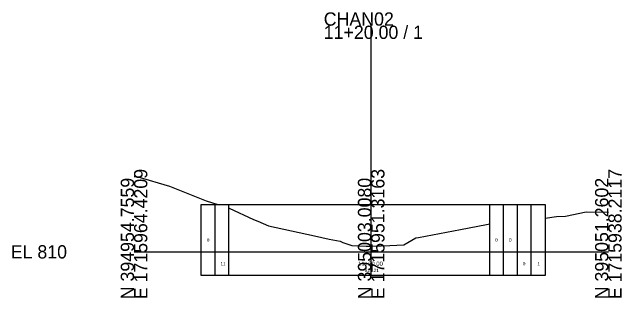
# Model space of a CAD drawing. Extents: x -26 to 103, y -10 to 16052.
# Drawn here: x -25.7 to 102.8, y 12490.3 to 12550.5 of the extents above; entities that cross this region are included whole.
import ezdxf

# ---------------------------------------------------------------- set-up
doc = ezdxf.new("R2010")
doc.units = 0
for name, color, linetype in [('GK_Cells', 7, 'Continuous'), ('SH_Text', 7, 'Continuous'), ('XS_P_Annotation', 7, 'Continuous'), ('XS_P_Boundary', 7, 'Continuous'), ('XS_X_Ground_Line', 7, 'Continuous')]:
    doc.layers.add(name, color=color, linetype=linetype)

msp = doc.modelspace()

# ---------------------------------------------------------------- linework, layer by layer
at = {"layer": 'GK_Cells'}
for p, q in [((50, 12500), (50, 12547.69)), ((0, 12500), (50, 12500)), ((50, 12500), (100, 12500))]:
    msp.add_line(p, q, dxfattribs=at)
at = {"layer": 'XS_P_Boundary'}
for p, q in [((17.08, 12495.01), (17.08, 12509.99)), ((20, 12495.01), (20, 12509.99)), ((50, 12495.01), (50, 12509.99)), ((75, 12495.01), (75, 12509.99)), ((77.92, 12495.01), (77.92, 12509.99)), ((80.83, 12495.01), (80.83, 12509.99)), ((83.75, 12495.01), (83.75, 12509.99)), ((15.63, 12502.5), (15.63, 12502.5)), ((76.46, 12502.5), (76.46, 12502.5)), ((79.38, 12502.5), (79.38, 12502.5)), ((18.54, 12497.51), (18.54, 12497.51)), ((82.29, 12497.51), (82.29, 12497.51)), ((85.21, 12497.51), (85.21, 12497.51))]:
    msp.add_line(p, q, dxfattribs=at)
msp.add_lwpolyline([(14.17, 12495.01), (14.17, 12509.99), (86.67, 12509.99), (86.67, 12495.01)], close=True, dxfattribs=at)
at = {"layer": 'XS_X_Ground_Line'}
for points in [[(0, 12515.9), (0.83, 12515.79), (7.5, 12513.87), (15.2, 12510.76), (17.64, 12509.99)], [(20, 12509.24), (20.07, 12509.22), (25.22, 12506.85), (26.13, 12506.46), (28.35, 12505.5), (38.06, 12503.35), (41.13, 12502.67), (43.44, 12502.22), (44.04, 12501.96), (45.95, 12501.32), (48.95, 12501.22), (50.27, 12501.21), (53.93, 12501.35), (56.85, 12501.48), (59.44, 12502.95), (59.96, 12503.02), (68.83, 12504.72), (74.3, 12505.75), (75, 12505.88)], [(86.67, 12507.12), (89.1, 12507.47), (90.97, 12507.55), (95.35, 12508.4), (100, 12508.35)]]:
    msp.add_lwpolyline(points, dxfattribs=at)

# ---------------------------------------------------------------- texts
at = {"layer": 'GK_Cells'}
for s, p in [('CHAN02', (40, 12547.69)), ('11+20.00 / 1', (40, 12544.89)), ('EL 810', (-26, 12498.6))]:
    msp.add_text(s, height=2.8, dxfattribs=at).set_placement(p)
for s, p in [('E 1715964.4209', (2.8, 12490)), ('E 1715951.3163', (52.8, 12490)), ('E 1715938.2117', (102.8, 12490)), ('N 394954.7559', (0, 12490)), ('N 395003.0080', (50, 12490)), ('N 395051.2602', (100, 12490))]:
    msp.add_text(s, height=2.8, rotation=90, dxfattribs=at).set_placement(p)
at = {"layer": 'SH_Text'}
for s, p in [('0', (15.35, 12502.15)), ('0', (76.14, 12502.15)), ('0', (79.06, 12502.15)), ('11', (18.23, 12497.16)), ('0', (81.98, 12497.16)), ('1', (85.06, 12497.16))]:
    msp.add_text(s, height=0.7, dxfattribs=at).set_placement(p)
at = {"layer": 'XS_P_Annotation'}
for s, height, p in [('11+20.00', 0.9, (47.25, 12497.05)), ('811.21', 0.7, (48.66, 12495.75))]:
    msp.add_text(s, height=height, dxfattribs=at).set_placement(p)

doc.saveas('drawing.dxf')
